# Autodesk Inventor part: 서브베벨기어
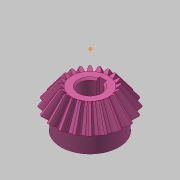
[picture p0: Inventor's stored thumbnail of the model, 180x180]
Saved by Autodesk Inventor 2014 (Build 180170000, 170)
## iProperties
Created: 2018-09
Part Number: 서브베벨기어
Material: 강철, 탄소
Document SubType Name: Modeling
Categories: <?xml version="1.0" encoding="UTF-16"?> <MemberInstance><Categories><FamilyTemplate><FamilyTemplateParameter ValueType="xs:double" Id="1" ObjectReferenceKey="da
Mass: 135.037 g
Surface Area: 63.6444 cm^2
Volume: 17.1585 cm^3
Density: 7.87 g/cm^3
Appearance: 분홍색
CustomPartVersion: 1
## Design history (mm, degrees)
node "맨 위 점"
node "메쉬 평면2"
sketch "톱니 본체 스케치"
  geometry: L1 (0, 0)-(18.003, -31.331); L2 (18.003, -31.331)-(21.664, -28.891); L3 (21.664, -28.891)-(0, 0); L4 (20, -30)-(0, 0); L5 (10.813, -18.818)-(13.012, -17.352); L6 (18.003, -31.331)-(10.813, -18.818); L7 (21.664, -28.891)-(13.012, -17.352); L8 (0, -39.387)-(0, 6.564) reference; L9 (0, -30)-(21.664, -30)
  constraints: 16 end point, 4 point on line, 3 perpendicular, 2 collinear, 1 horizontal alignment, 1 vertical alignment
  dimensions: "d0" = 40 diameter of L4.start L8 (= da_de); "d1" = 36.00616 diameter of L1.end L8 (= da_dfe); "d2" = 43.3282 diameter of L2.end L8 (= da_dae); "d3" = 14.4 distance between parallel lines of L2 L5 (= da_b); "d4" = 28.8906 vertical distance of L2.end L1.start (= da_ve)
revolve "톱니 본체" sketch "톱니 본체 스케치" stored, may be unused: angle "d5" = 90 deg
node "시작점"
node "톱니 평면"
sketch "시작 스케치"
  geometry: L1 (0, -23.505)-(0, 10.645) reference; L2 (-0.834, -2.928)-(0.834, -2.928); A1 r 8.898 centre (-9.698, -3.713) between (-0.834, -2.928) and (-3.903, 3.04); A2 r 8.898 centre (9.698, -3.713) between (3.903, 3.04) and (0.834, -2.928); A3 r 27.357 centre (0, -24.037) between (3.903, 3.04) and (-3.903, 3.04); 1 further point
  constraints: 6 point on circle, 3 centre point, 3 symmetric about line, 2 end point, 1 coincident, 1 perpendicular, 1 other
  dimensions: "d7" = 8.89846 radius of A1 (= fd_rr); "d8" = 9.69794 horizontal distance of point (0, -24.037) A1.centre (= fd_x); "d9" = 20.32439 vertical distance of point (0, -24.037) A1.centre (= fd_y); "d57" = 27.35701 radius of A3 (= 0.5 x fd_dva + 0.3 x da_he); "d58" = 21.10901 distance from line of A3.centre L2 (= 0.5 x fd_dva - 1.12 x da_he)
node "끝점"
  node "끝 평면"
sketch "3D 스케치 오른쪽"
  node "Helical Curve Right" dims "d65" = 229.90621 (computed from da_dm, da_delta, da_beta), "d66" = 31.5, "d67" = 40 (= da_de), "d68" = -5.88003 (= -da_delta), "d69" = 12.16458 (computed from fd_loft, da_delta)
node "끝 평면 오른쪽"
sketch "끝 스케치 오른쪽"
  geometry: L1 (0, -22.649)-(0, 12.15) reference; L2 (-0.497, -1.72)-(0.497, -1.72); A1 r 5.299 centre (-5.775, -2.187) between (-0.497, -1.72) and (-2.324, 1.834); A2 r 5.299 centre (5.775, -2.187) between (2.324, 1.834) and (0.497, -1.72); A3 r 16.291 centre (0, -14.29) between (2.324, 1.834) and (-2.324, 1.834); 1 further point
  constraints: 6 point on circle, 3 centre point, 3 symmetric about line, 2 end point, 1 coincident, 1 perpendicular, 1 other
  dimensions: "d70" = 5.77526 horizontal distance of A3.centre A1.centre (computed from fd_x, fd_ratio); "d71" = 12.10346 vertical distance of point (0, -14.29) A1.centre (computed from fd_y, fd_ratio); "d72" = 5.29916 radius of A1 (computed from fd_rr, fd_ratio); "d73" = 12.57071 distance from line of point (0, -14.29) L2 (computed from d58, fd_ratio); "d74" = 16.29149 radius of A3 (computed from d57, fd_ratio)
feature "로프트 오른쪽" sketch "끝 스케치 오른쪽" dims "d75" = 0, "d77" = 0, "d79" = 0, "d80" = 90 deg, "d85" = 20, "d92" = 90 deg, "d93" = 90 deg, "da_teethtype" = 0 [user parameter]
sketch "3D 스케치 왼쪽"
  node "Helical Curve Left" dims "d26" = 229.90621 (computed from da_dm, da_delta, da_beta), "d27" = 12.16458 (computed from fd_loft, da_delta), "d28" = 40 (= da_de), "d29" = -5.88003 (= -da_delta)
node "끝 평면 왼쪽"
sketch "끝 스케치 왼쪽" dims "d56" = 10.82768 (derived)
  geometry: L1 (0, -35.087)-(0, 18.089) reference; L2 (-0.497, -1.716)-(0.497, -1.716); A1 r 5.299 centre (-5.775, -2.183) between (-0.497, -1.716) and (-2.324, 1.838); A2 r 5.299 centre (5.775, -2.183) between (2.324, 1.838) and (0.497, -1.716); A3 r 16.291 centre (0, -14.287) between (2.324, 1.838) and (-2.324, 1.838); 2 further points; 1 other entity
  constraints: 6 point on circle, 3 centre point, 3 symmetric about line, 2 end point, 1 coincident, 2 other
  dimensions: "d30" = 5.29916 radius of A1 (computed from fd_rr, fd_ratio); "d31" = 5.77526 horizontal distance of point (0, -14.287) A1.centre (computed from fd_x, fd_ratio); "d32" = 12.10346 vertical distance of A1.centre point (0, -14.287) (computed from fd_y, fd_ratio); "d61" = 16.29149 radius of A3 (computed from d57, fd_ratio); "d62" = 12.57071 distance from line of point (0, -14.287) L2 (computed from d58, fd_ratio)
feature "로프트 왼쪽" sketch "끝 스케치 왼쪽" dims "d35" = 0, "d37" = 0, "d39" = 0, "d40" = 90 deg, "d84" = 10, "d90" = 90 deg, "d91" = 90 deg, "da_teethtype" = 0 [user parameter]
sketch "본체 스케치"
  geometry: L1 (0, -35.038)-(0, -19.531) reference; L2 (18.003, -31.331)-(10.813, -18.818) reference; L3 (10.813, -18.818)-(0, -18.818); L4 (18.003, -31.331)-(0, -31.331)
  constraints: 4 end point, 2 perpendicular, 2 point on line
revolve "본체 고정" sketch "본체 스케치" stored, may be unused: angle "d46" = 90 deg
feature "피치 지름" dims angle "d47" = 90 deg
sketch "스케치8"
  geometry: C1 r 17 at (0, 0); 1 further point
  constraints: 1 centre point, 1 coincident
  dimensions: "d94" = 34 diameter of C1
extrude "돌출1" join sketch "스케치8" distance "d95" = 10; taper "d96" = 0 deg
sketch "스케치9"
  geometry: 1 further point
hole "구멍1" sketch "스케치9" at (0, 0) diameter "d97" = 12; stored, may be unused: countersink angle "d101" = 90 deg, drill point angle "d103" = 118 deg; dims "d98" = 6, "d99" = 4, "d100" = 2, "d102" = 8
sketch "스케치10"
  geometry: 1 further point
sketch "스케치11"
  geometry: 1 further point
sketch "스케치12"
  geometry: L1 (-2, 5.657)-(-2, 7.8); L2 (-2, 7.8)-(2, 7.8); L3 (2, 7.8)-(2, 5.657); A1 r 6 centre (0, 0) between (-2, 5.657) and (2, 5.657) reference; 1 further point
  constraints: 6 end point, 2 parallel, 2 point on circle, 1 perpendicular, 1 vertical
  dimensions: "d104" = 4 distance of L1.end L2.end; "d105" = 13.8 dimension on A1 L2
extrude "돌출2" cut sketch "스케치12" stored distance "d106" = 7; taper "d107" = 0 deg
chamfer "모따기1" distance "d108" = 1; stored, may be unused: second distance "d109" = 2, angle "d110" = 45 deg
body "Solid1"
feature "로프트" dims "d17" = 0, "d18" = 90 deg, "d19" = 0, "d20" = 90 deg, "d89" = 0, "da_teethtype" = 0 [user parameter]
pattern_circular "원형 패턴" dims angle "d22" = 360 deg, "d88" = 0, "da_teethtype" = 0 [user parameter]
pattern_circular "원형 패턴 오른쪽" dims angle "d82" = 360 deg, "da_teethtype" = 0 [user parameter]
pattern_circular "원형 패턴 왼쪽" dims angle "d42" = 360 deg, "da_teethtype" = 0 [user parameter]
sketch "끝 스케치"
  geometry: L1 (0, -15.359)-(0, 6.983) reference; L2 (-0.497, -1.72)-(0.497, -1.72); A1 r 5.299 centre (-5.775, -2.187) between (-0.497, -1.72) and (-2.324, 1.834); A2 r 5.299 centre (5.775, -2.187) between (2.324, 1.834) and (0.497, -1.72); A3 r 16.291 centre (0, -14.29) between (2.324, 1.834) and (-2.324, 1.834); 1 further point
  constraints: 6 point on circle, 3 centre point, 3 symmetric about line, 2 end point, 1 coincident, 1 other
  dimensions: "d12" = 5.29916 radius of A1 (computed from fd_rr, fd_ratio); "d15" = 5.77526 horizontal distance of A1.centre point (0, -14.29) (computed from fd_x, fd_ratio); "d16" = 12.10346 vertical distance of A1.centre point (0, -14.29) (computed from fd_y, fd_ratio); "d59" = 16.29149 radius of A3 (computed from d57, fd_ratio); "d60" = 12.57071 distance from line of A3.centre L2 (computed from d58, fd_ratio)
sketch "Sketch6"
  geometry: L1 (20, -30)-(0, 0) reference; L2 (0, -37.8)-(0, 6.3) reference
body "Srf1"
other parameters: "da_b" = 14.4 [user parameter; used in 2 equation terms], "da_de" = 40 [user parameter; used in 4 equation terms], "da_dae" = 43.3282 [user parameter; used in 2 equation terms], "da_dfe" = 36.00616 [user parameter; used in 1 equation term], "da_le" = 36.05551 [user parameter; used in 1 equation term], "da_omega" = 90 deg [user parameter; used in 1 equation term], "da_beta" = 0 [user parameter; used in 2 equation terms], "da_delta" = 5.88003 [user parameter; used in 8 equation terms], "da_alpha" = 20 deg [user parameter; used in 2 equation terms], "da_he" = 4.4 [user parameter; used in 4 equation terms], "da_ve" = 28.8906 [user parameter; used in 1 equation term], "fd_dv" = 48.07402 (computed from da_de, da_delta) [user parameter; used in 1 equation term], "fd_dva" = 52.07402 (computed from da_dae, da_delta) [user parameter; used in 3 equation terms], "fd_dvb" = 45.1748 (computed from fd_dv, da_alpha) [user parameter; used in 2 equation terms], "da_zv" = 240.37008 [user parameter; used in 1 equation term], "fd_loft" = 14.62 (= da_b + 0.05 x da_he) [user parameter; used in 4 equation terms], "fd_ratio" = 5.95514 (computed from da_le, fd_loft) [user parameter; used in 15 equation terms], "fd_rr" = 8.89846 (computed from fd_dd, fd_dvb) [user parameter; used in 6 equation terms], "fd_angle" = 0.66075 (computed from da_zv) [user parameter; used in 4 equation terms], "fd_x1" = 1.58709 (computed from da_dvw, fd_angle) [user parameter; used in 1 equation term], "fd_y1" = 23.98456 (computed from da_dvw, fd_angle) [user parameter; used in 1 equation term], "fd_x2" = 8.11084 (computed from fd_rr, fd_angle2, fd_angle) [user parameter; used in 1 equation term], "fd_y2" = 3.66016 (computed from fd_rr, fd_angle2, fd_angle) [user parameter; used in 1 equation term], "fd_x" = 9.69794 (= fd_x1 + fd_x2) [user parameter; used in 4 equation terms], "fd_y" = 20.32439 (= fd_y1 - fd_y2) [user parameter; used in 4 equation terms], "fd_angle2" = 3.57832 (computed from fd_dvb, fd_dd, da_alpha) [user parameter; used in 2 equation terms], "fd_dd" = 48.55402 (= fd_dva - 0.8 x da_he) [user parameter; used in 2 equation terms], "da_dvw" = 48.07402 [user parameter; used in 2 equation terms], "d11" = 14.62 (= fd_loft), "da_dm" = 32.01232 [user parameter; used in 2 equation terms], "da_x" = 0 [user parameter], "da_m" = 2 [user parameter], "d48" = 0, "d49" = 0, "d50" = 90 deg (= da_omega), "d51" = 9 deg (computed from da_z), "d52" = 0, "d53" = 0, "d54" = 0
